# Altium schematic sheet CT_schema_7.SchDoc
size 430 x 429 mm
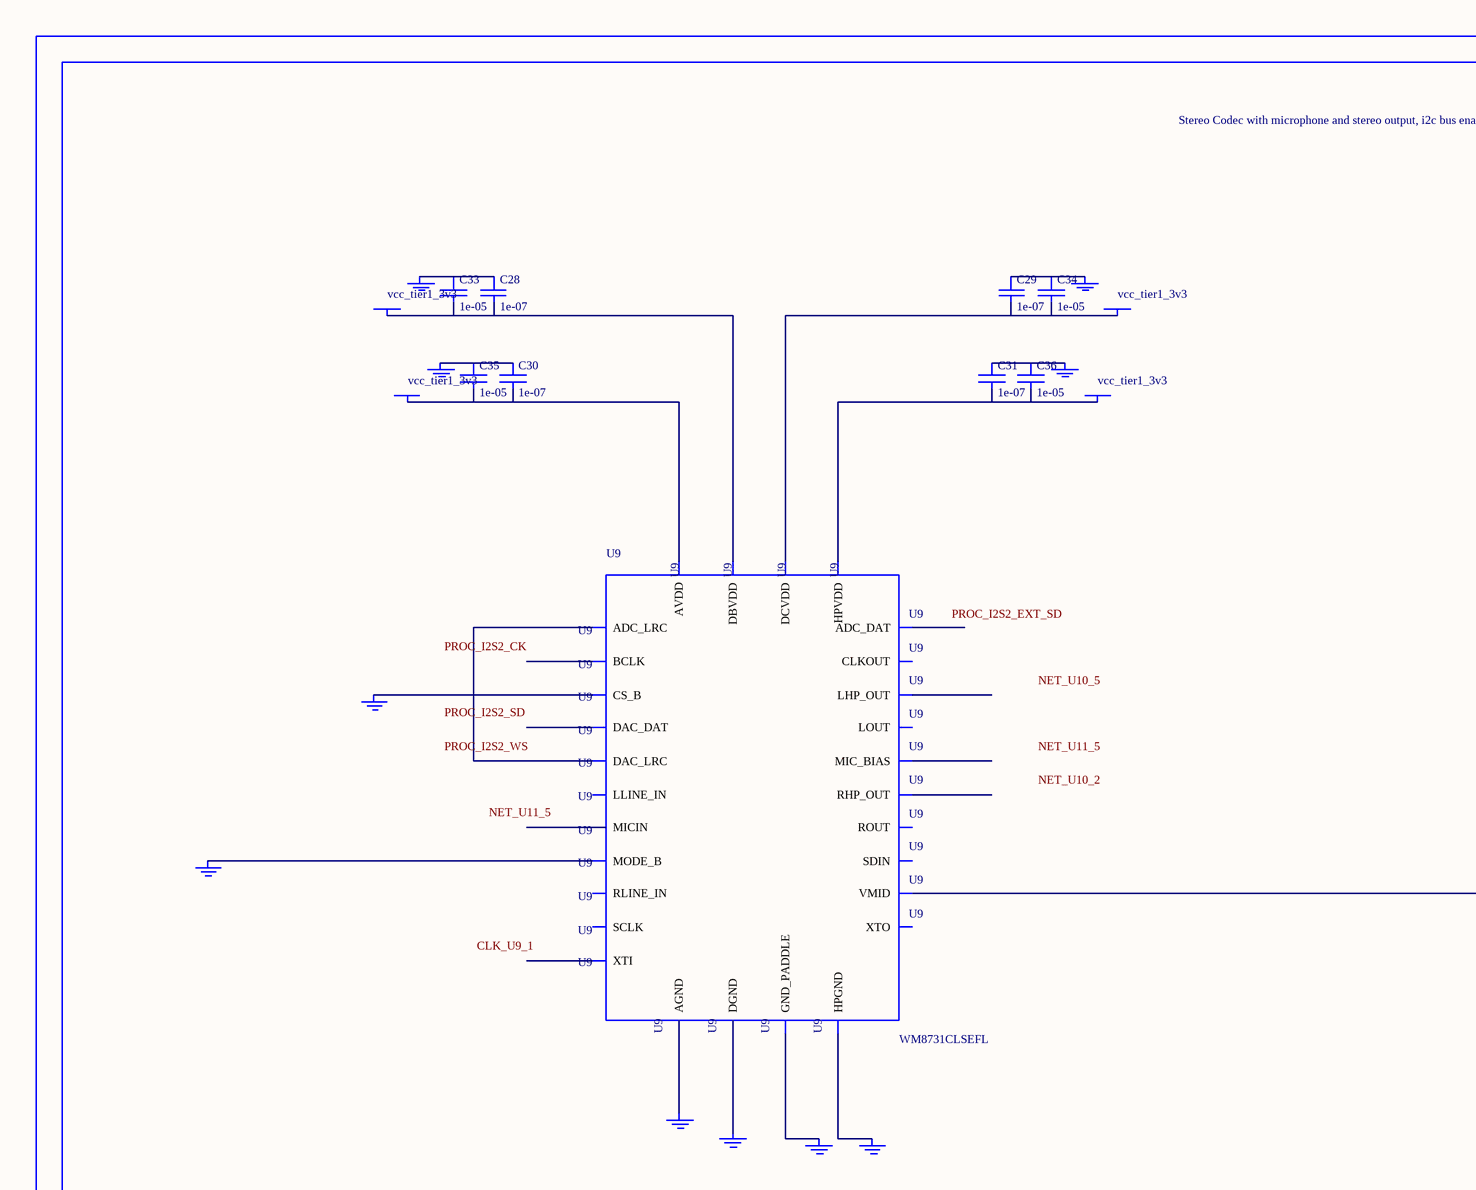
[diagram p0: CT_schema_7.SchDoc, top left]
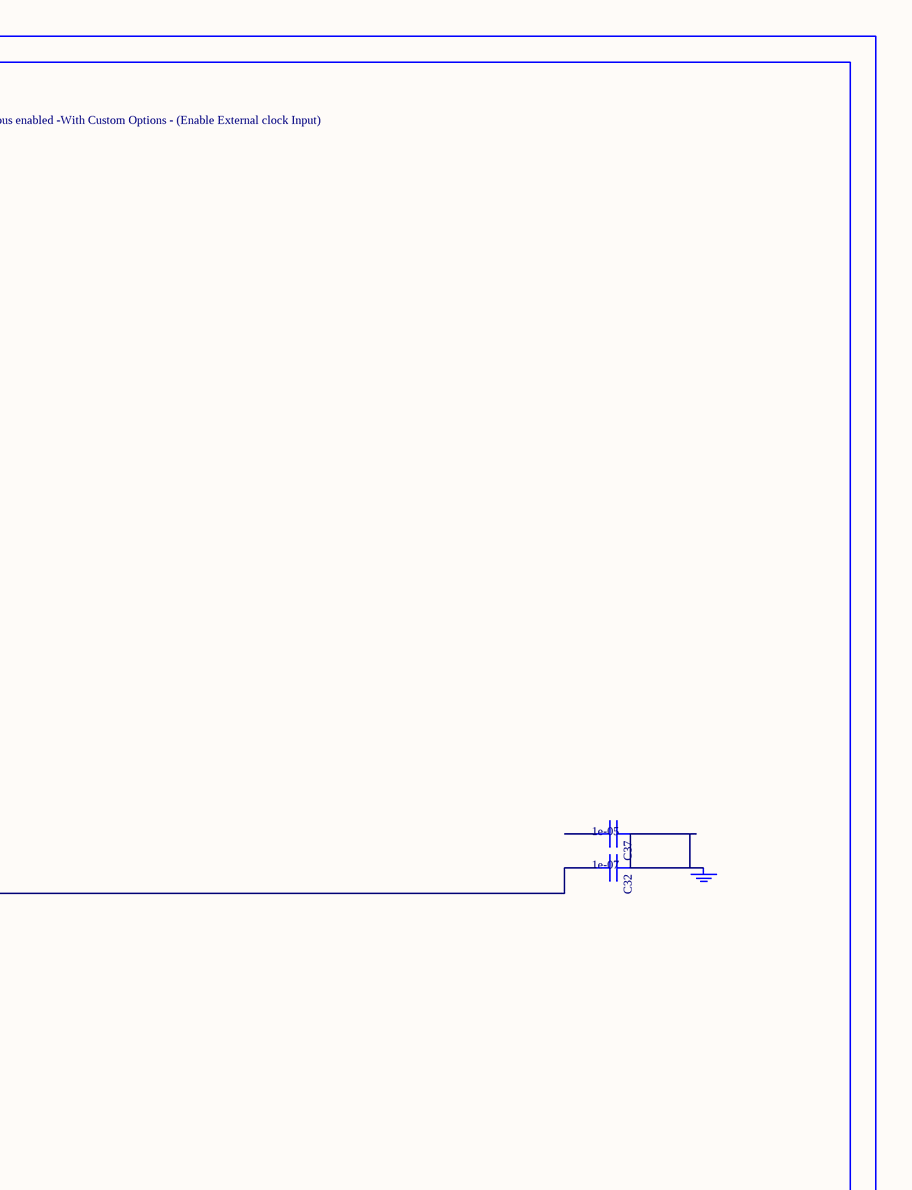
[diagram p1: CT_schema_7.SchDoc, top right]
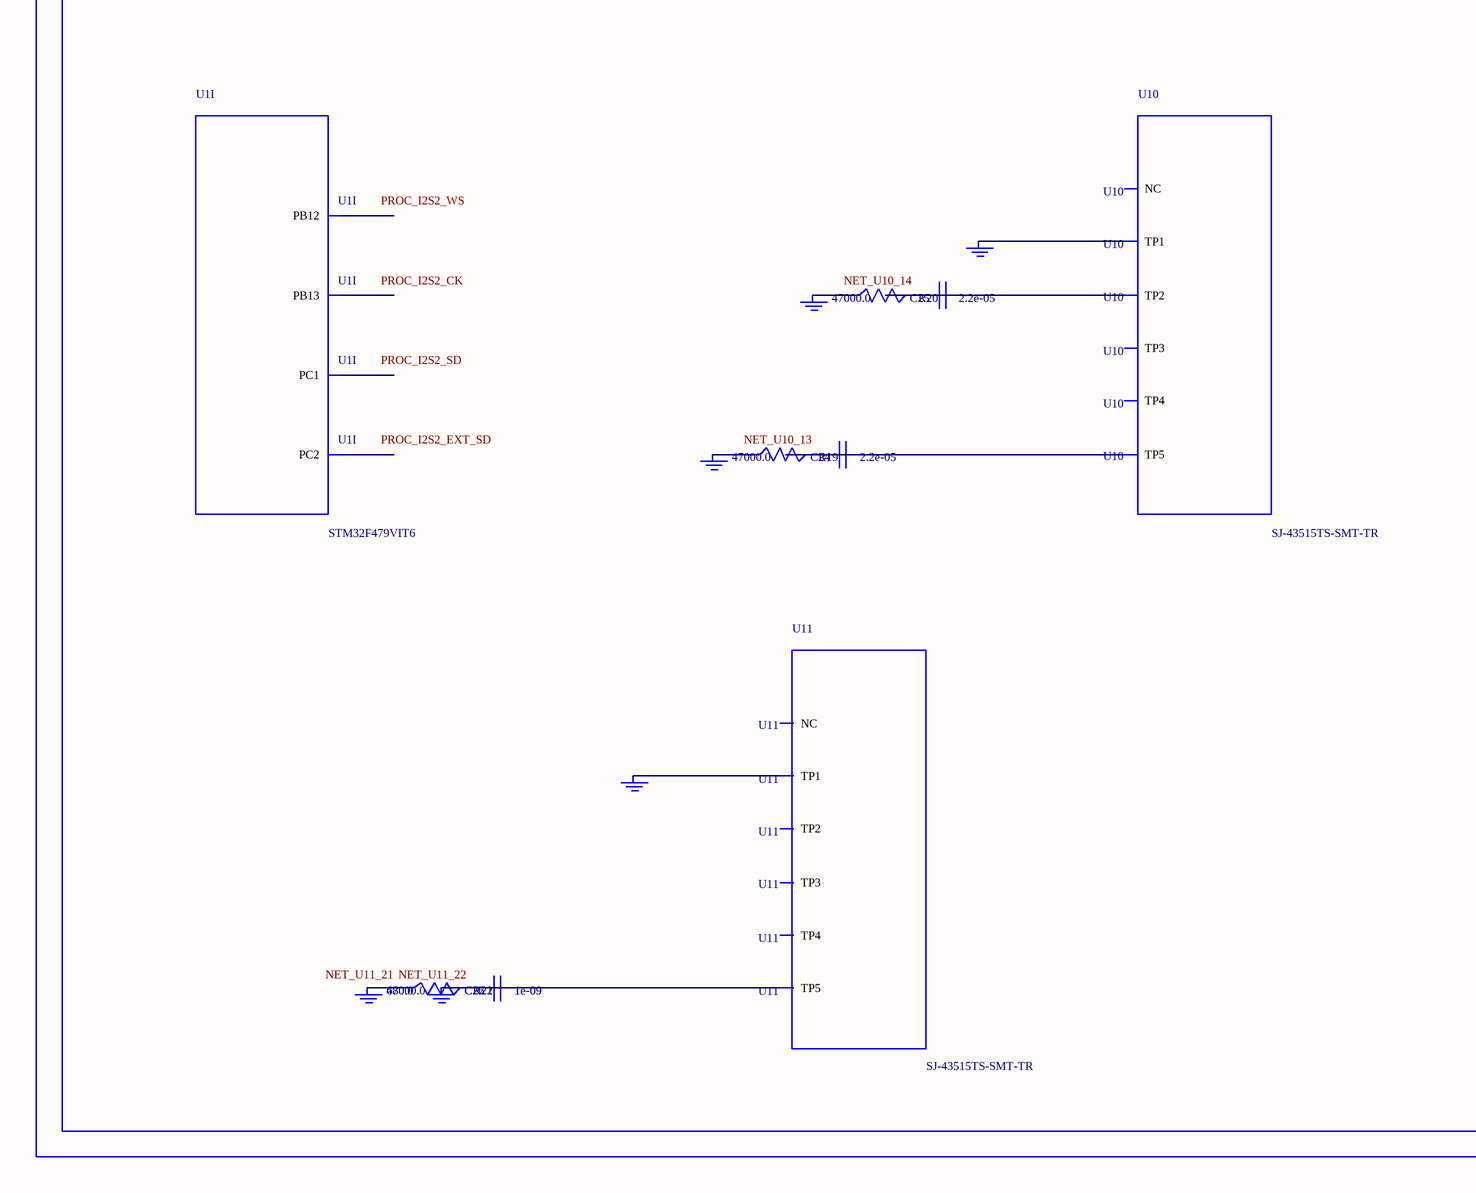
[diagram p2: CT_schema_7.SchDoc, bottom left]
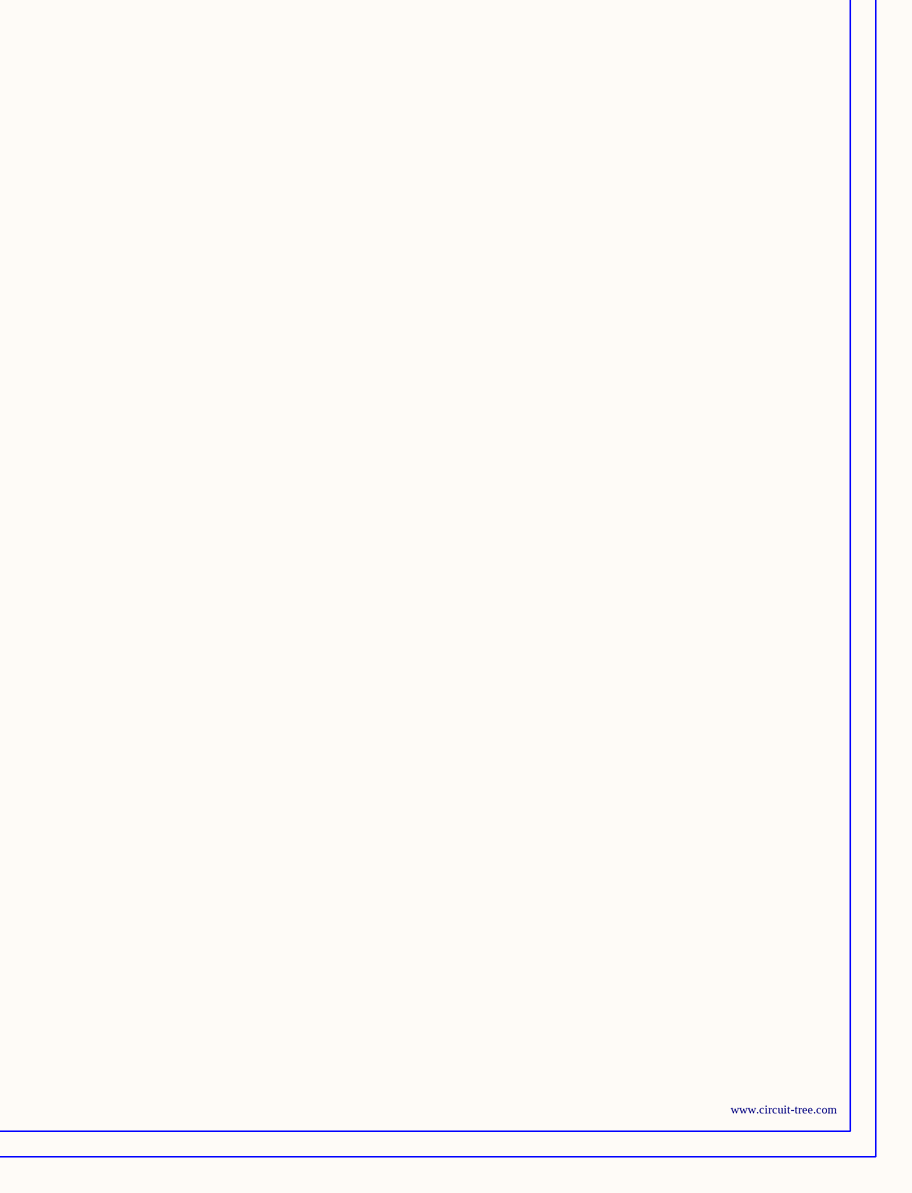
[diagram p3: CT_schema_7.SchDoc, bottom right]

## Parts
BORDER6  (no value)
C24  2.2e-05  [C1210]
C25  2.2e-05  [C1210]
C26  1e-09  [C0402]
C27  1e-09  [C0402]
C28  1e-07  [C0402]
C29  1e-07  [C0402]
C30  1e-07  [C0402]
C31  1e-07  [C0402]
C32  1e-07  [C0402]
C33  1e-05  [C0805]
C34  1e-05  [C0805]
C35  1e-05  [C0805]
C36  1e-05  [C0805]
C37  1e-05  [C0805]
GND_INSTANCE_6_0  (no value)
GND_INSTANCE_6_1  (no value)
GND_INSTANCE_6_2  (no value)
GND_INSTANCE_6_3  (no value)
GND_INSTANCE_6_4  (no value)
GND_INSTANCE_6_5  (no value)
GND_INSTANCE_6_6  (no value)
GND_INSTANCE_6_7  (no value)
GND_INSTANCE_6_8  (no value)
GND_INSTANCE_6_9  (no value)
GND_INSTANCE_6_10  (no value)
GND_INSTANCE_6_11  (no value)
GND_INSTANCE_6_12  (no value)
GND_INSTANCE_6_13  (no value)
GND_INSTANCE_6_14  (no value)
GND_INSTANCE_6_15  (no value)
GND_INSTANCE_6_16  (no value)
POWER_INSTANCE_6_0  vcc_tier1_3v3
POWER_INSTANCE_6_1  vcc_tier1_3v3
POWER_INSTANCE_6_2  vcc_tier1_3v3
POWER_INSTANCE_6_3  vcc_tier1_3v3
R19  47000.0  [R0603]
R20  47000.0  [R0603]
R21  47000.0  [R0603]
R22  680.0  [R0603]
U1  STM32F479VIT6  [LQFP100]  (part I of 9)
U9  WM8731CLSEFL  [QFN-28]
U10  SJ-43515TS-SMT-TR  [SJ-43515TS-SMT-TR]
U11  SJ-43515TS-SMT-TR  [SJ-43515TS-SMT-TR]

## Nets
NetC24_1: C24.1 C24.2 R19.2 U10.5(TP5)
NetC25_1: C25.1 C25.2 R20.2 U10.2(TP2)
NetC26_1: C26.1 C26.2 C27.1 C27.2 GND_INSTANCE_6_16.0(GND) R21.2 R22.2 U11.5(TP5)
NetC28_1: C28.1 C33.1 GND_INSTANCE_6_1.0(GND)
NetC28_2: C28.2 C33.2 POWER_INSTANCE_6_1.0(PWR) U9.5(DBVDD)
NetC29_1: C29.1 C34.1 GND_INSTANCE_6_0.0(GND)
NetC29_2: C29.2 C34.2 POWER_INSTANCE_6_0.0(PWR) U9.3(DCVDD)
NetC30_1: C30.1 C35.1 GND_INSTANCE_6_4.0(GND)
NetC30_2: C30.2 C35.2 POWER_INSTANCE_6_3.0(PWR) U9.18(AVDD)
NetC31_1: C31.1 C36.1 GND_INSTANCE_6_2.0(GND)
NetC31_2: C31.2 C36.2 POWER_INSTANCE_6_2.0(PWR) U9.12(HPVDD)
NetC32_1: C32.1 C37.1 GND_INSTANCE_6_5.0(GND)
NetC32_2: C32.2 U9.20(VMID)
NetGND_INSTANCE_6_3_0: GND_INSTANCE_6_3.0(GND) U9.15(HPGND)
NetGND_INSTANCE_6_6_0: GND_INSTANCE_6_6.0(GND) U9.25(MODE_B)
NetGND_INSTANCE_6_7_0: GND_INSTANCE_6_7.0(GND) U9.26(CS_B)
NetGND_INSTANCE_6_8_0: GND_INSTANCE_6_8.0(GND) U9.29(GND_PADDLE)
NetGND_INSTANCE_6_9_0: GND_INSTANCE_6_9.0(GND) U9.4(DGND)
NetGND_INSTANCE_6_10_0: GND_INSTANCE_6_10.0(GND) U9.19(AGND)
NetGND_INSTANCE_6_11_0: GND_INSTANCE_6_11.0(GND) U10.1(TP1)
NetGND_INSTANCE_6_12_0: GND_INSTANCE_6_12.0(GND) R20.1
NetGND_INSTANCE_6_13_0: GND_INSTANCE_6_13.0(GND) R19.1
NetGND_INSTANCE_6_14_0: GND_INSTANCE_6_14.0(GND) U11.1(TP1)
NetGND_INSTANCE_6_15_0: GND_INSTANCE_6_15.0(GND) R21.1 R22.1
NetU9_9: U9.9(DAC_LRC) U9.11(ADC_LRC)

Not connected (* = marked no-connect by the designer): C37 2; U1 13(PC1) 14(PC2) 46(PB12) 47(PB13); U9 1(XTI) 2(XTO) 6(CLKOUT) 7(BCLK) 8(DAC_DAT) 10(ADC_DAT) 13(LHP_OUT) 14(RHP_OUT) 16(LOUT) 17(ROUT) 21(MIC_BIAS) 22(MICIN) 23(RLINE_IN) 24(LLINE_IN) 27(SDIN) 28(SCLK); U10 3(TP3) 4(TP4) 6(NC); U11 2(TP2) 3(TP3) 4(TP4) 6(NC)

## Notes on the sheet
- Labels drawn without touching a wire or pin: CLK_U9_1, NET_U10_2, NET_U10_5, NET_U10_13, NET_U10_14, NET_U11_5, NET_U11_21, NET_U11_22, PROC_I2S2_CK, PROC_I2S2_EXT_SD, PROC_I2S2_SD, PROC_I2S2_WS

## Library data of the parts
BORDER6 = BORDER_PAGE6
C24 C25 = C1210C224K5RACTU
C26 C27 = C0402C102K3RAC
C28-C32 = C0402C104K3RACTU
C33-C37 = C0805C106K8RACTU
GND_INSTANCE_6_0-GND_INSTANCE_6_16 = GND
POWER_INSTANCE_6_0-POWER_INSTANCE_6_3 = PWR
R19-R21 = RC0603JR-0747KL
R22 = RC0603JR-07680RL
